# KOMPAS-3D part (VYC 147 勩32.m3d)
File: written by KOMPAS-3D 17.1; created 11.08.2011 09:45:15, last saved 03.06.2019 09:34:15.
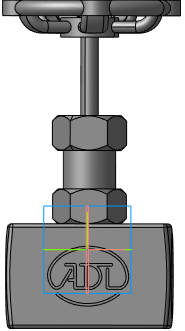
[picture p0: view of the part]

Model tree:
1. Плоскость XY
2. Плоскость ZX
3. Плоскость ZY
4. Ось X
5. Ось Y
6. Ось Z
7. Начало координат
8. Операция без истории:2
